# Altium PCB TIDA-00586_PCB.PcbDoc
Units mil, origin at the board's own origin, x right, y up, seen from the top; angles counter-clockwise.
Board outline 4500 x 1700 mil, 4 copper layers (Top Layer, MidLayer1, MidLayer2, Bottom Layer), stack 61.2 mil thick; 69 components, 46 nets, 255 pads, 91 vias.
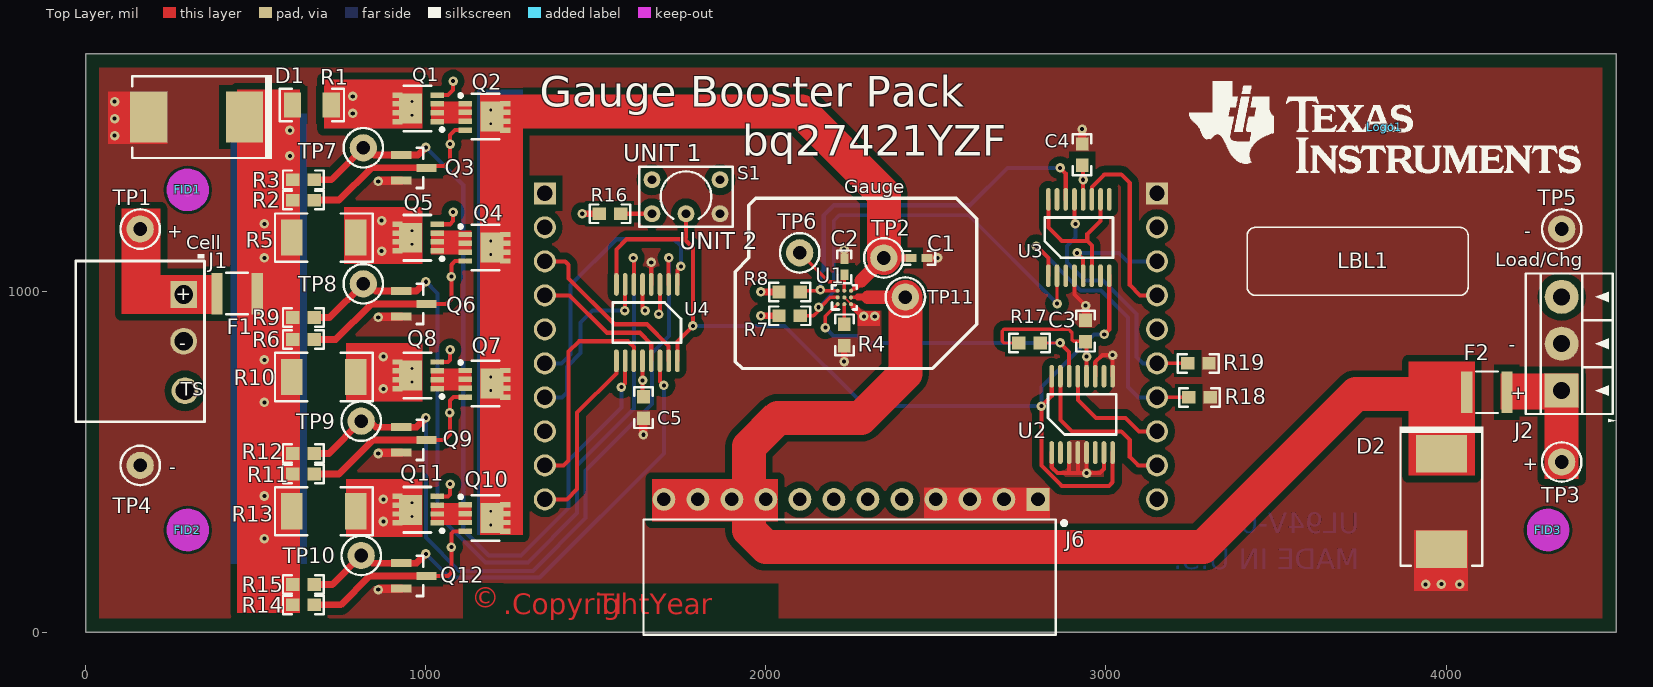
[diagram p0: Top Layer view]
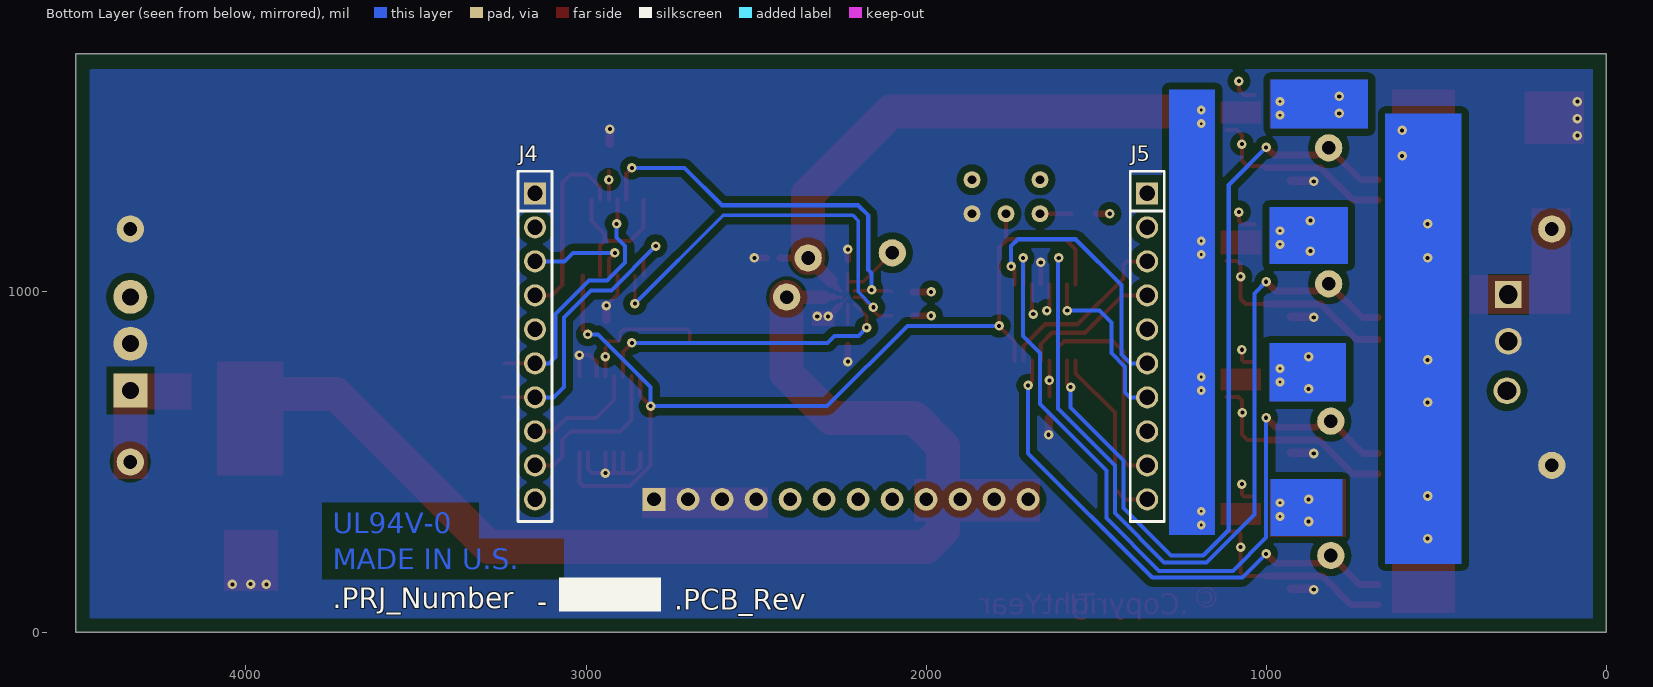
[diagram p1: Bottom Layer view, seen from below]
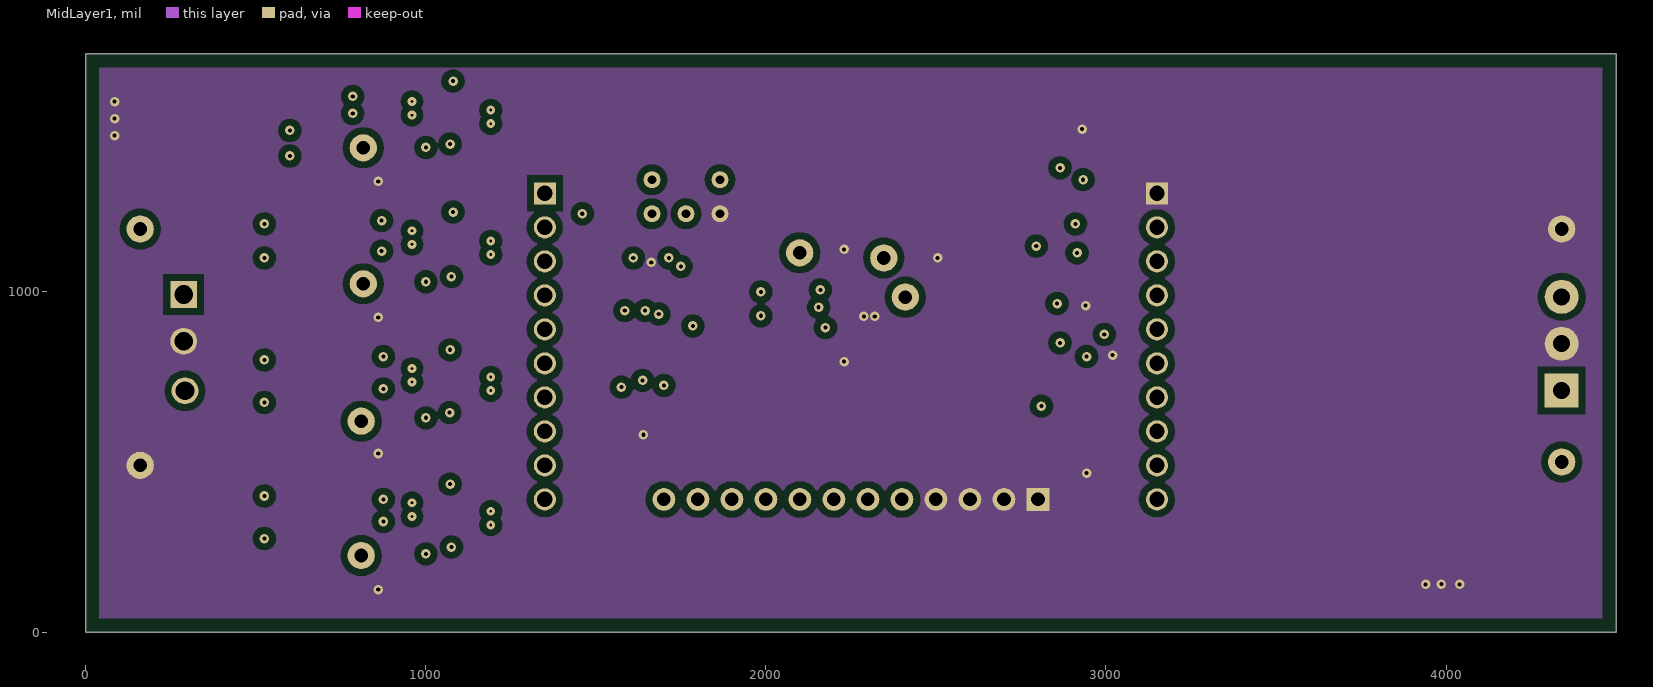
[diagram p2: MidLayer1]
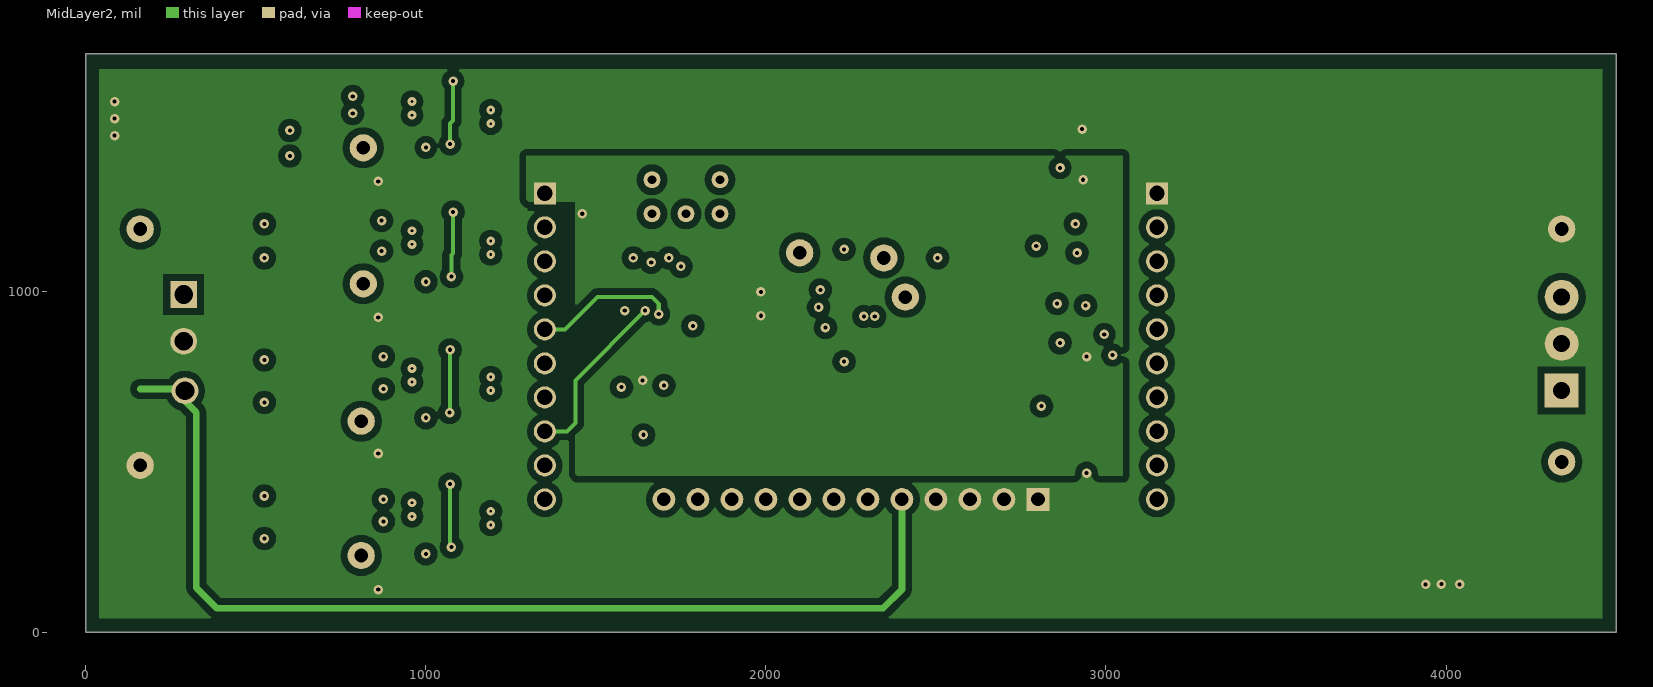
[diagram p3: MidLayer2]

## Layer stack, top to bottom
Top Solder: solder mask 0.4, Solder Resist, Dk 3.5
Top Layer: signal copper 2.8
Dielectric1: core 8, FR-4, Dk 4.8
MidLayer1: signal copper 2.8
Dielectric2: prepreg 34, FR-4, Dk 4.8
MidLayer2: signal copper 2.8
Dielectric3: core 8, FR-4, Dk 4.8
Bottom Layer: signal copper 2.8
Bottom Solder: solder mask 0.4, Solder Resist, Dk 3.5

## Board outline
0,0 0,1700 4500,1700 4500,0 0,0

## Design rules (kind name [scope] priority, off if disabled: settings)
AcuteAngle [All] p1: minimum=4.50000000000000E+0001 checktracksonly=FALSE
AssemblyTestPointUsage [All] p1: valid=2
Clearance Clearance_BoardEdge_MountingHoles [OnCopper and InComponentClass('Mounting Holes') vs IsKeepOut] p1: gap=8
Clearance Clearance_BoardEdge_Poly [OnCopper and InPoly vs IsKeepOut] p2: gap=8
Clearance Clearance_BoardEdge [OnCopper and Not InComponentClass('Logo') and not InComponentClass('FiducialMark') and not InRegion(1000,500,4000,800) and Not IsKeepout vs IsKeepOut] p3: gap=20
Clearance Clearance_Poly [InPolygon] p4: gap=20
Clearance [All] p5: gap=5
ComponentClearance ComponentClearance_Shunt [InComponentClass('Header') vs InComponentClass('Shunt')] p1: gap=0 collisioncheckmode=3 verticalgap=0 showdistances=FALSE
ComponentClearance ComponentClearance_Logo [InComponentClass('Logo')] p2: gap=5 collisioncheckmode=3 verticalgap=5 showdistances=FALSE
ComponentClearance ComponentClearance_ScrewToNut [(HasFootprint('NY PMS 440 0025 PH')) vs (HasFootprint('Keystone_1902C'))] p3: gap=5 collisioncheckmode=3 verticalgap=10 showdistances=FALSE
ComponentClearance ComponentClearance_MountingHoles [InComponentClass('Mounting Holes')] p4: gap=250 collisioncheckmode=3 verticalgap=100000 showdistances=FALSE
ComponentClearance ComponentClearance_SmallPassives [HasFootprint('0201*') or HasFootprint('0402*') or HasFootprint('0508') or HasFootprint('0603*') or HasFootprint('0612') or HasFootprint('0805*') or HasFootprint('0815*') or HasFootprint('0830*') or HasFootprint('1206*') or HasFootprint('1210*') or HasFootprint('1808*') or HasFootprint('1812*') or HasFootprint('1825*') or HasFootprint('2010*') or HasFootprint('2220*') or HasFootprint('2225*') or HasFootprint('2512*') or HasFootprint('2728*') or HasFootprint('3518*') vs HasFootprint('0201*') or HasFootprint('0402*') or HasFootprint('0508') or HasFootprint('0603*') or HasFootprint('0612') or HasFootprint('0805*') or HasFootprint('0815*') or HasFootprint('0830*') or HasFootprint('1206*') or HasFootprint('1210*') or HasFootprint('1808*') or HasFootprint('1812*') or HasFootprint('1825*') or HasFootprint('2010*') or HasFootprint('2220*') or HasFootprint('2225*') or HasFootprint('2512*') or HasFootprint('2728*') or HasFootprint('3518*')] p5: gap=8 collisioncheckmode=3 verticalgap=8 showdistances=FALSE
ComponentClearance ComponentClearance_THtoSMT [IsThruComponent vs IsSMTComponent] p6: gap=8 collisioncheckmode=3 verticalgap=8 showdistances=FALSE
ComponentClearance ComponentClearance_THtoTH [IsThruComponent vs IsThruComponent] p7: gap=8 collisioncheckmode=3 verticalgap=8 showdistances=FALSE
ComponentClearance [All] p8: gap=8 collisioncheckmode=3 verticalgap=8 showdistances=FALSE
DiffPairsRouting [All] p1: maxlimit=100 minlimit=10 mostfreqgap=10 toplayer_minwidth=15 toplayer_maxwidth=15 toplayer_prefwidth=15 midlayer1_minwidth=15 midlayer1_maxwidth=15 midlayer1_prefwidth=15 midlayer2_minwidth=15 midlayer2_maxwidth=15 midlayer2_prefwidth=15 bottomlayer_minwidth=15 bottomlayer_maxwidth=15 bottomlayer_prefwidth=15 maxuncoupledlength=1000
FabricationTestPointUsage TestPointUsage [All] p1: valid=2 allowmultiple=FALSE
FabricationTestpoint Testpoint [All] p1: side=3 testpointundercomponent=TRUE minsize=40 maxsize=100 preferedsize=60 minholesize=0 maxholesize=40 preferedholesize=32 testpointgrid=1 allowsidetop=TRUE allowsidebottom=TRUE usegrid=TRUE gridtolerance=0.01
FanoutControl Fanout_LCC [IsLCC] p1: bgadir=Out bgaviamode=Centered fanoutstyle=Auto fanoutdirection=Alternating viagrid=1 // Fanout_LCC (Default Rule)
FanoutControl Fanout_BGA [IsBGA] p2: bgadir=Out bgaviamode=Centered fanoutstyle=Auto fanoutdirection=Alternating viagrid=1 // Fanout_BGA (Default Rule)
FanoutControl Fanout_Default [All] p4: bgadir=Out bgaviamode=Centered fanoutstyle=Auto fanoutdirection=Alternating viagrid=1 // Fanout_Default (Default Rule)
FanoutControl Fanout_Small [(CompPinCount < 5)] p5: bgadir=Out bgaviamode=Centered fanoutstyle=Auto fanoutdirection=OutThenIn viagrid=1 // Fanout_Small (Default Rule)
HoleSize [All] p1: absolutevalues=TRUE maxlimit=251 minlimit=5 maxpercent=80.000 minpercent=20.000
MinimumAnnularRing MinimumAnnularRing_ThermalPadVias [IsVia and InAnyComponent] p1: minimumring=5
MinimumAnnularRing [All] p2: minimumring=5
MinimumSolderMaskSliver MinimumSolderMaskSliver_Logo [InComponentClass('Logo') vs InComponentClass('Logo')] p1: minsoldermaskwidth=0.7
MinimumSolderMaskSliver [All] p2: minsoldermaskwidth=3.94
PlaneClearance [All] p1: clearance=10
PlaneConnect [All] p1: planeconnectstyle=Direct reliefexpansion=10 reliefentries=4 reliefconductorwidth=10 reliefairgap=10
PolygonConnect [All] p1: connectstyle=Direct reliefconductorwidth=10 reliefentries=4 polygonreliefangle="90 Angle" airgapwidth=10
RoutingVias ThermalPadVias [IsVia and InAnyComponent] p1: holewidth=7.87 width=19.68 viastyle="Through Hole" minholewidth=7.87 minwidth=19.68 maxholewidth=12.99 maxwidth=23.62
RoutingVias [All] p2: holewidth=12 width=24 viastyle="Through Hole" minholewidth=5 minwidth=10 maxholewidth=40 maxwidth=65
SMDToCorner [All] p1: distance=30000
SilkToSilkClearance [All] p1: silktosilkclearance=5
SilkToSolderMaskClearance SilkscreenOverComponentPads [IsPad] p1: minsilkscreentomaskgap=5 clearancetoexposedcopper=TRUE
SolderMaskExpansion [All] p1: expansion=1.97
UnpouredPolygon [All] p1: allowunpoured=FALSE
Width [All] p1: maxlimit=100 minlimit=6 preferedwidth=10 checkconnectedcopper=TRUE
14 further rules are at their usual default settings.

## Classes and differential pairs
component class Logo: Logo1
component class PR2183E3_Hdwr: FID1 FID2 FID3 LBL1 Logo1 ZZ1 ZZ2 ZZ3
component class FiducialMark: FID1 FID2 FID3
component class AssemblyNote: ZZ1 ZZ2 ZZ3
component class Label: LBL1
component class PR2183E3_Gauge: C1 C2 C3 C4 C5 D1 D2 F1 F2 J1 J2 J4 J5 J6 Q1 Q2 Q3 Q4 Q5 Q6 Q7 Q8 Q9 Q10 Q11 Q12 R1 R2 R3 R4 R5 R6 R7 R8 R9 R10 R11 R12 R13 R14 R15 R16 R17 R18 R19 S1 TP1 TP2 TP3 TP4 TP5 TP6 TP7 TP8 TP9 TP10 TP11 U1 U2 U3 U4

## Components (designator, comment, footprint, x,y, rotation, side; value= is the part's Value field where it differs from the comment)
C1 "GRM155R61A105KE15D" 0402 2450,1100 r0 top
C2 "GRM155R60J474KE19D" 0402 2230.63,1073.88 r90 top
C3 "C0603C104K3RACTU" 0603 2940,885 r90 top
C4 "C0603C104K3RACTU" 0603 2930,1403.7 r90 top
C5 "C0603C104K3RACTU" 0603 1640,660 r270 top
D1 "1.5SMC6.8A" SMC 326.16,1514 r180 top
D2 "1.5SMC6.8A" SMC 3986.16,384 r270 top
F1 "RF1824-000" FUSE_LR2 445,995 r0 top
F2 "RF1824-000" FUSE_LR2 4120,705 r0 top
FID1 "Fiducial" Fiducial10-30 300,1300 r0 top
FID2 "Fiducial" Fiducial10-30 300,300 r0 top
FID3 "Fiducial" Fiducial10-30 4300,300 r0 top
J1 "OSTOQ031251" On-Shore_OSTOQ031251 160,855 r270 top
J2 "ED555/3DS" TERM_BLK_ED555-3DS 4340,710 r90 top
J4 "SSW-110-24-F-S" CONN_SSW-110-23-F-S 3150,1290 r90 bottom locked
J5 "SSW-110-24-F-S" CONN_SSW-110-23-F-S 1350,1290 r90 bottom locked
J6 "PPPC121LGBN-RC" SULLINS_PPPC121LGBN-RC 2250,390 r0 top locked
LBL1 "Size: 0.65\" x 0.20 \"" Label_650x200 3740,1090 r0 top
Logo1 "Texas Instruments" TI_Stacked_Overlay_Medium 3820,1485 r0 top
Q1 "SI7615ADN-T1-GE3" PowerPAK_1212-8 975,1540 r180 top
Q2 "SI7615ADN-T1-GE3" PowerPAK_1212-8 1175,1515 r0 top
Q3 "2N7002-7-F" SOT-23 965,1365 r0 top
Q4 "SI7615ADN-T1-GE3" PowerPAK_1212-8 975,1160 r180 top
Q5 "SI7615ADN-T1-GE3" PowerPAK_1212-8 1175,1130 r0 top
Q6 "2N7002-7-F" SOT-23 965,965 r0 top
Q7 "SI7615ADN-T1-GE3" PowerPAK_1212-8 975,755 r180 top
Q8 "SI7615ADN-T1-GE3" PowerPAK_1212-8 1175,730 r0 top
Q9 "2N7002-7-F" SOT-23 965,565 r0 top
Q10 "SI7615ADN-T1-GE3" PowerPAK_1212-8 975,360 r180 top
Q11 "SI7615ADN-T1-GE3" PowerPAK_1212-8 1175,335 r0 top
Q12 "2N7002-7-F" SOT-23 965,165 r0 top
R1 "CRCW12060000Z0EA" 1206 665,1550 r0 top
R2 "CRCW06032M00FKEA" 0603 640,1270 r180 top
R3 "CRCW06032M00FKEA" 0603 640,1330 r180 top
R4 "CRCW0603100KFKEA" 0603 2230.63,873.88 r90 top
R5 "CSRN2010FKR100" 2010M 700,1160 r0 top
R6 "CRCW06032M00FKEA" 0603 640,860 r180 top
R7 "CRCW06031K00FKEA" 0603 2070,930 r180 top
R8 "CRCW06031K00FKEA" 0603 2070,1000 r180 top
R9 "CRCW06032M00FKEA" 0603 640,925 r180 top
R10 "CSRN2010FKR200" 2010M 700,750 r0 top
R11 "CRCW06032M00FKEA" 0603 640,465 r180 top
R12 "CRCW06032M00FKEA" 0603 640,525 r180 top
R13 "CSRN2010FKR400" 2010M 700,355 r0 top
R14 "CRCW06032M00FKEA" 0603 640,80 r180 top
R15 "CRCW06032M00FKEA" 0603 640,140 r180 top
R16 "CRCW060310K0FKEA" 0603 1541.65,1230 r180 top
R17 "CRCW06031M00FKEA" 0603 2775,850 r180 top
R18 "CRCW06032M00FKEA" 0603 3275,690 r180 top
R19 "CRCW06032M00FKEA" 0603 3271.5,790 r180 top
S1 "G12AP" SW_G1xAP 1765,1280 r0 top
TP1 "5000" Keystone5000 160,1185 r0 top
TP2 "5000" Keystone5000 2346.75,1100 r0 top
TP3 "5000" Keystone5000 4340,500 r0 top
TP4 "5001" Keystone5001 160,490 r0 top
TP5 "5001" Keystone5001 4340,1185 r0 top
TP6 "5000" Keystone5000 2099.35,1115 r0 top
TP7 "5002" Keystone5002 816.16,1424 r0 top
TP8 "5002" Keystone5002 816.16,1024 r0 top
TP9 "5002" Keystone5002 810,620 r0 top
TP10 "5002" Keystone5002 810,225 r90 top
TP11 "5000" Keystone5000 2410,985 r0 top
U1 "BQ27421YZFR-G1A" YZF0009AKAL 2230.66,983.85 r90 top
U2 "TS3A44159PWR" PW0016A_N 2930,640 r90 top
U3 "TS3A44159PWR" PW0016A_N 2920,1160 r90 top
U4 "TS3A44159PWR" PW0016A_N 1650,910 r270 top
ZZ1 "This Assembly Note is for PCB labels only" AssemblyNoteLabel 205,7588 r0 top
ZZ2 "Mating Plug" AssemblyNote 205,7479.11 r0 top
ZZ3 "J4, J5 Must be inserted from the bottom with the pins facing up." AssemblyNote 205,7365 r0 top

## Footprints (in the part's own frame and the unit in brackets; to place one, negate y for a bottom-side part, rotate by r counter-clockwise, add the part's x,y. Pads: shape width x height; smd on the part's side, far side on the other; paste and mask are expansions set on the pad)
0402 [mm] "0402 from SM-752 data"
  rect 0.8x0.6 smd: 1(-0.6,0) 2(0.6,0)
  silkscreen extent -1.22,-0.52 1.22,0.52, body extent -0.55,-0.3 0.55,0.3, height 0.6
0603 [mm] "0603 from SM-752 data"
  rect 1x0.95 smd: 1(-0.8,0) 2(0.8,0)
  silkscreen extent -1.52,-0.69 1.52,0.69, body extent -0.87,-0.47 0.87,0.47, height 0.85
1206 [mm] "1206 from SM-752 data"
  rect 1.3x1.85 smd: 1(-1.45,0) 2(1.45,0)
  silkscreen extent -2.4,-1.21 2.4,1.21, body extent -1.7,-0.9 1.7,0.9, height 1.35
2010M [mm]
  rect 1.6x2.7 smd: 1(-2.4,0) 2(2.4,0)
  silkscreen extent -3.65,-1.8 3.65,1.8, body extent -2.73,-1.45 2.73,1.45, height 1.66
AssemblyNote [mil] "Assembly Note"
AssemblyNoteLabel [mil] "Assembly Note for PCB Labels"
CONN_SSW-110-23-F-S [mm] "SAMTEC"
  rect 1.65x1.65 hole 1.15: 1(0,0)
  round 1.65 hole 1.15: 2(-2.54,0) 3(-5.08,0) 4(-7.62,0) 5(-10.16,0) 6(-12.7,0) 7(-15.24,0) 8(-17.78,0) 9(-20.32,0) 10(-22.86,0)
  silkscreen extent -24.51,-1.27 1.65,1.27, body extent -24.43,-1.27 1.57,1.27, height 8.59
Fiducial10-30 [mm]
  round 1 smd paste-0.5 mask+1: 1(0,0)
  Top Layer keep-out circle w1.678: c0,0 r0.75
FUSE_LR2 [mm] "TE Connectivity"
  rect 0.85x3.1 smd: 1(-1.5,0) 2(1.5,0)
  silkscreen extent -0.8,-1.55 0.8,1.55, body extent -1.71,-1.4 1.71,1.4, height 1
Keystone5000 [mil] "For Keystone 500x miniature loop terminals"
  round 80 hole 40: 1(0,0)
  silkscreen extent -58,-58 58,58, body extent -49,-49 49,49, height 182
Keystone5001 [mil] "For Keystone 500x miniature loop terminals"
  round 80 hole 40: 1(0,0)
  silkscreen extent -58,-58 58,58, body extent -49,-49 49,49, height 182
Keystone5002 [mil] "For Keystone 500x miniature loop terminals"
  round 80 hole 40: 1(0,0)
  silkscreen extent -58,-58 58,58, body extent -49,-49 49,49, height 182
Label_650x200 [mil] "Thermal Transfer Label"
  round 1 on Mech13: 0(0,0)
  silkscreen extent -325,-100 325,100, body extent -326,-101 326,101, height 1
On-Shore_OSTOQ031251 [mm] "TERM BLOCK 3x1, 3.5mm, TH"
  rect 2x2 hole 1.4: 1(-3.5,3.25)
  round 2 hole 1.4: 2(0,3.25) 3(3.7,3.35)
  silkscreen extent -6.5,-4.8 6,4.8, body extent -5.95,-4.75 5.95,4.75, height 7
PowerPAK_1212-8 [mil] "Vishay PowerPAK 1212-8, Body 3.4x3.2mm (max), Pitch 0.65mm, IPC Medium Density"
  rect 39x16 smd mask+2.01: 1(-58.75,39) 2(-58.75,13) 3(-58.75,-13) 4(-58.75,-39)
  rect 30x16 smd mask+2.01: 5(58.75,-39) 6(58.75,-13) 7(58.75,13) 8(58.75,39)
  rect 68x88 smd mask+2.01: 9(19.75,0.61)
  silkscreen extent -78,-66 40,68, body extent -65,-65 65,65, height 43
PW0016A_N [mm] "TSOP, 16-Leads, Body 5x4.4mm, Pitch 0.65mm, IPC Medium Density"
  oval 1.7x0.35 smd: 1(-2.85,2.275) 2(-2.85,1.625) 3(-2.85,0.975) 4(-2.85,0.325) 5(-2.85,-0.325) 6(-2.85,-0.975) 7(-2.85,-1.625) 8(-2.85,-2.275) 9(2.85,-2.275) 10(2.85,-1.625) 11(2.85,-0.975) 12(2.85,-0.325) 13(2.85,0.325) 14(2.85,0.975) 15(2.85,1.625) 16(2.85,2.275)
  silkscreen extent -1.5,-2.55 1.5,2.55, body extent -3.21,-2.5 3.21,2.5, height 0.98
SMC [mil] "Molded Diode, 2-Leads, Body 6.9x5.8mm, IPC Medium Density, based on OnSemi component dimensions and land patterns"
  rect 110x150 smd: 1(-140.49,0) 2(140.49,0)
  silkscreen extent -221,-124 189,123, body extent -156,-116 156,116, height 91
SOT-23 [mm] "SOT23, 3-Leads, Body 2.9x1.3mm, Pitch 0.95mm, Lead Span 2.5mm, IPC Medium Density"
  rect 1.5x0.6 smd: 1(-0.95,0.95) 2(-0.95,-0.95) 3(0.95,0)
  silkscreen extent 0.2,-1.5 0.7,1.5, body extent -1.16,-1.45 1.21,1.45, height 1
SULLINS_PPPC121LGBN-RC [mm] "SULLINS"
  rect 1.7x1.7 hole 1.016: 1(13.97,0)
  round 1.7 hole 1.016: 2(11.43,0) 3(8.89,0) 4(6.35,0) 5(3.81,0) 6(1.27,0) 7(-1.27,0) 8(-3.81,0) 9(-6.35,0) 10(-8.89,0) 11(-11.43,0) 12(-13.97,0)
  silkscreen extent -15.49,-10.1 16.07,-1.5, body extent -15.49,-10.08 15.24,0.23, height 2.52
SW_G1xAP [mil] "Switch, NKK G Series"
  round 50 hole 26: 1(-100,50) 3(100,50) 4(-100,-50) 5(0,-50) 6(100,-50)
  silkscreen extent -138,-88 138,89, body extent -138,-88 138,89, height 424
TERM_BLK_ED555-3DS [mm]
  rect 2.54x2.54 hole 1.27: 1(0,0)
  round 2.54 hole 1.27: 2(3.5,0) 3(7,0)
  silkscreen extent -2.36,-4.09 8.75,2.67, body extent -1.75,-3.83 8.75,2.67, height 8.2
TI_Stacked_Overlay_Medium [mil]
  silkscreen extent -576,-136 576,134
YZF0009AKAL [mm] "BGA, 9-Leads, Body 1.6205x1.58mm, Pitch 0.5mm"
  round 0.3 smd paste-0.15 mask+0.05: A1(-0.5,0.5) A2(0,0.5) A3(0.5,0.5) B1(-0.5,0) B2(0,0) B3(0.5,0) C1(-0.5,-0.5) C2(0,-0.5) C3(0.5,-0.5)
  silkscreen extent -0.9,-0.93 0.9,0.93, body extent -0.8,-0.83 0.8,0.83, height 0.63

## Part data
C1: "CAP, CERM, 1uF, 10V, +/-10%, X5R, 0402"
C2: "CAP, CERM, 0.47uF, 6.3V, +/-10%, X5R, 0402"
C3 C4 C5: "CAP, CERM, 0.1uF, 25V, +/-10%, X7R, 0603"
D1 D2: "Diode, TVS, Uni, 6.8V, 1500W, SMC"
F1 F2: "Fuse, Resettable, 1.9A, 6V, SMD"
FID1 FID2 FID3: "Fiducial mark.  There is nothing to buy or mount."
J1: "Header, 3x1 3.5mm, TH"
J2: "Terminal Block, 6A, 3.5mm Pitch, 3-Pos, TH"
J4 J5: library part SSW-110-23-F-S, "Connector, Receptacle, 100mil, 10x1, Gold plated, TH"
J6: "Header, 12x1, 100mil, R/A, TH"
LBL1: library part THT-14-423-10, "Thermal Transfer Printable Labels, 0.650\" W x 0.200\" H - 10,000 per roll"
Logo1: library part TI_Logo, "Texas Instrument Corporate Signature"
Q1 Q2 Q4 Q5 Q7 Q8 Q10 Q11: "MOSFET, P-CH, -20V, -22.1A, PowerPAK 1212"
Q3 Q6 Q9 Q12: "MOSFET, N-CH, 60V, 0.17A, SOT-23"
R1: "RES, 0 ohm, 5%, 0.25W, 1206"
R2 R3 R6 R9 R11 R12 R14 R15 R18 R19: "RES, 2.00Meg ohm, 1%, 0.1W, 0603"
R4: "RES, 100k ohm, 1%, 0.1W, 0603"
R5: "RES, 0.1 ohm, 1%, 1W, 2010"
R7 R8: "RES, 1.00k ohm, 1%, 0.1W, 0603"
R10: "RES, 0.2 ohm, 1%, 1W, 2010"
R13: "RES, 0.4 ohm, 1%, 1W, 2010"
R16: "RES, 10.0k ohm, 1%, 0.1W, 0603"
R17: "RES, 1.00Meg ohm, 1%, 0.1W, 0603"
S1: "Switch, Toggle, SPDT 1Pos, TH"
TP1 TP2 TP3 TP6 TP11: "Test Point, Miniature, Red, TH"
TP4 TP5: "Test Point, Miniature, Black, TH"
TP7 TP8 TP9 TP10: "Test Point, Miniature, White, TH"
U1: "System-Side Impedance Track Fuel Gauge With Integrated Sense Resistor, YZF0009AKAL"
U2 U3 U4: "0.45 ohm QUAD SPDT ANALOG SWITCH QUAD-CHANNEL 2:1 MULTIPLEXER/DEMULTIPLEXER WITH TWO CONTROLS, PW0016A"
ZZ1: library part AssemblyNoteLabel
ZZ2: library part AssemblyNote, "This is the mating Plug for Connector J1"
ZZ3: library part AssemblyNote

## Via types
v1: diameter 28, hole 12, Top Layer to Bottom Layer, 75 vias
v2: diameter 26, hole 8, Top Layer to Bottom Layer, tented top, 16 vias

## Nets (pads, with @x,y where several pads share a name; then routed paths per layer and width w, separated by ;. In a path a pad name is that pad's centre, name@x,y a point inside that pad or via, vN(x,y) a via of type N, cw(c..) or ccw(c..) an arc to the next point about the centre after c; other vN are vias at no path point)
3.3VDC: C3.1 C4.1 C5.1 J5.1 R7.2 R8.2 R16.2 R17.2 U2.12 U3.12 U4.12 | length 762.2
  Top Layer w10: R17.2 2700,850 2695,855 2695,885 2700,890 2890,890 2900,880 2900,860 2905,855 2938.5,855 C3.1
  Top Layer w12: C5.1@1637.2,694.29 v1(1637.2,740) U4.12 ; U3.12 v1(2932.8,1330) C4.1@2932.8,1355.71 ; U2.12 v1(2942.8,810) C3.1@2942.8,835.71
  Top Layer w20: v1(1460,1230) R16.2@1500.18,1230 ; v1@1990,930 R7.2 ; v1@1990,1000 R8.2
  other v1: 1985,930 1985,1000
B1_1: J5.3 U4.15 | length 517.9
  Top Layer w12: J5.3@1370,1100 1380,1090 1410,1090 1420,1080 1420,1040 1555,905 1650,905 1713.98,841.02 U4.15
B1_2: J5.4 U4.13 | length 405.5
  Top Layer w12: J5.4@1370,1000 1380,990 1422.15,990 1532.15,880 1630,880 1662.8,847.2 U4.13
B2_1: J5.5 U4.3 | length 480.6
  Top Layer w12: v1@1688.39,938.39 U4.3
  MidLayer2 w12: J5.5@1370,900 1380,890 1409.25,890 1504.25,985 1665,985 1685,965 v1(1685,935)
B2_2: J5.6 U4.1 | length 780.3
  Top Layer w12: U4.1 1739.57,1064.57 v1(1750,1075)
  Bottom Layer w12: J5.6@1370,800 1380,790 1399.14,790 1425,815.86 1425,1020 1560,1155 1730,1155 1750,1135 v1(1750,1075)
B3_1: J5.7 U4.7 | length 491.6
  Top Layer w12: v1@1586.02,946.02 U4.7
  Bottom Layer w12: J5.7@1374.25,695.75 1380,690 1400,690 1415,705 1415,780 1455,820 1455,910 1490,945 v1(1585,945)
B3_2: J5.8 U4.5 | length 569.4
  Top Layer w12: v1@1637.2,952.2 U4.5
  MidLayer2 w12: J5.8@1370,600 1380,590 1415,590 1440,615 1440,740 v1(1645,945)
B4_1: J5.9 U4.11 | length 631.9
  Top Layer w12: J5.9@1370,500 1380,490 1405,490 1420,505 1420,825 1450,855 1595,855 1611.61,838.39 U4.11
B4_2: J5.10 U4.9 | length 517.2
  Top Layer w12: J5.10@1370,400 1380,390 1415,390 1445,420 1445,645 1560.43,760.43 U4.9
BIN: R4.2 U1.B1 | length 58.8
  Top Layer w10: R4.2@2230.66,905.41 U1.B1
BINARY_1: Q12.1 R15.1 TP10.1 U4.14 | length 1542.3
  Top Layer w12: U4.14 1688.39,736.61 v1(1700,725)
  Top Layer w20: R15.1 725,140 TP10.1 820,225 842.6,202.4 Q12.1 972.4,202.4 v1(1000,230)
  Bottom Layer w12: v1(1000,230) 1070,160 1335,160 1700,525 v1(1700,725)
BINARY_2: Q9.1 R12.1 TP9.1 U4.2 | length 2256.5
  Top Layer w12: U4.2 v1@1713.98,1098.98
  Top Layer w20: R12.1 715,525 TP9.1 834.97,620 852.57,602.4 Q9.1 972.4,602.4 v1(1000,630)
  Bottom Layer w12: v1(1000,630) 1000,278.15 1098.15,180 1315,180 1470,335 1470,475 1665,670 1665,820.77 1715,870.77 v1(1715,1100)
BINARY_3: Q6.1 R9.1 TP8.1 U4.6 | length 2513.3
  Top Layer w12: U4.6 v1@1611.61,1098.39
  Top Layer w20: R9.1 717.16,925 TP8.1 831,1024 852.6,1002.4 Q6.1 972.4,1002.4 v1(1000,1030)
  Bottom Layer w12: v1(1000,1030) 1034.23,995.77 1034.23,345.77 1175,205 1300,205 1445,350 1445,490 1611.61,656.61 1611.61,1098.39 v1(1610,1100)
BINARY_4: Q3.1 R3.1 TP7.1 U4.10 | length 2456.9
  Top Layer w12: v1(1575,720) 1586.02,731.02 U4.10
  Top Layer w20: R3.1 722.16,1330 TP7.1 826,1424 847.6,1402.4 Q3.1 977.4,1402.4 v1(1000,1425)
  Bottom Layer w12: v1(1000,1425) 1110,1315 1110,300 1185,225 1280,225 1420,365 1420,505 1575,660 v1(1575,720)
CHG/LOAD: D2.1 F2.1 J6.9 J6.10 J6.11 J6.12 TP11.1 U1.C2 | length 3355.8
  Top Layer w11: U1.C2@2250.36,983.85 2270,985
  Top Layer w20: 2270,985 2300,985
  Top Layer w40: 2300,985 TP11.1@2400,985
  Top Layer w100: 1950,390 1950,300 2000,250 3285,250 3735,700 3950,700 ; 1950,410 1950,545 2035,630 2280,630 2410,760 TP11.1
CS_1: J4.4 U3.11 | length 549.9
  Top Layer w12: U3.11 2958.39,1308.39 2995,1345 3045,1345 3070,1320 3070,1020 3100,990 3120,990 J4.4@3130,1000
CS_2: J4.3 U3.5 | length 304.1
  Top Layer w12: v1(2915,1115) 2932.8,1097.2 U3.5
  Bottom Layer w12: v1(2915,1115) 3038.88,1115 3063.88,1090 3120,1090 J4.3@3130,1100
GND: C1.2 C2.2 C3.2 C4.2 C5.2 D1.2 D2.2 J1.2 J2.2 J4.1 J6.1 J6.2 J6.3 J6.4 Q3.2 Q6.2 Q9.2 Q12.2 R4.1 R18.1 R19.1 S1.6 TP4.1 TP5.1 U1.B2 U1.C1 U2.1 U2.3 U2.4 U2.5 U2.7 U2.9 U2.11 U3.4 U4.4 | length 2169.5
  Top Layer w6: U1.B2 U1.C1@2250.36,964.15
  Top Layer w12: U4.4 v1(1662.8,1087.2) ; U1.C1@2250.36,964.15 2258.74,955.77 ; U2.1 2840.43,484.57 2857.2,467.8 2890,467.8 2891.61,469.41 U2.3 ; 2891.61,467.8 2917.2,467.8 ; U3.4 2907.2,992.8 v1(2940,960) ; U2.4 2917.2,467.8 ; U2.5 v1(2942.8,467.2) ; U2.11 2968.39,793.39 2989.57,814.57 v1(3019.57,814.57) U2.9 ; U2.7 2993.98,478.98 2982.2,467.2 v1(2942.8,467.2) ; 2917.2,467.8 2917.8,467.2 v1(2942.8,467.2)
  Top Layer w20: v1@2230.63,800.63 R4.1 ; C2.2@2230.63,1093.57 C2.2 v1@2230.63,1124.37 ; 2258.74,955.77 2280,934.51 2280,920 v1(2288,928) v1@2290,930 ; C1.2@2469.69,1100 C1.2 v1(2505,1100)
  Top Layer w25: v1(85,1460) 185,1460 185.67,1460.67 D1.2 ; v1@86,1514 D1.2 ; v1@90,1560 185,1560 185.67,1559.33 D1.2 ; v1@862.6,127.6 Q12.2 ; v1@862.6,527.6 Q9.2 ; v1@862.6,927.6 Q6.2 ; v1@862.6,1327.6 Q3.2 ; v1(1640,580) C5.2 ; C4.2 v1(2930,1478.7) ; C3.2 v1(2940,960) ; v1(3940,140) 3940,240 3943.51,243.51 D2.2 ; v1(3986.16,141.16) D2.2 ; v1(4040,140) 4040,240 4036.49,243.51 D2.2
  other v1: 860,125 860,525 2230,795 860,925 2320,928 2230,1125 860,1325 85,1510 85,1560
GPOUT: R17.1 U1.A1 U2.14 | length 960
  Top Layer w10: v1(2175,895) 2175,928.19 U1.A1 ; R17.1 v1(2865,850)
  Top Layer w12: v1(2865,850) 2891.61,823.39 U2.14
  Bottom Layer w12: v1(2175,895) 2199.25,870.75 2268.74,870.75 2289.5,850 v1(2865,850)
GPOUT_1: J4.9 U2.15 | length 478.3
  Top Layer w12: U2.15 2866.02,623.98 2900,590 3045,590 3070,565 3070,515 3095,490 3120,490 J4.9@3128,498
GPOUT_2: J4.8 U2.13 | length 310.6
  Top Layer w12: U2.13 2917.2,682.8 2970.24,629.76 3057.31,629.76 3097.07,590 J4.8@3120,590
I2C_SCL_B: J4.6 R19.2 U3.13 | length 729.6
  Top Layer w10: J4.6 R19.2
  Top Layer w12: v1@2907.2,1202.8 U3.13
  Bottom Layer w12: v1(2910,1200) 2910,1160 2885,1135 2885,1086.23 2937.62,1033.62 2991.38,1033.62 3090,935 3090,808.34 3108.34,790 3120,790 J4.6@3130,800
I2C_SDA_B: J4.7 R18.2 U3.1 | length 857.9
  Top Layer w10: J4.7 R18.2@3246.95,690
  Top Layer w12: v1(2795,1135) 2830.43,1099.57 U3.1
  Bottom Layer w12: v1(2795,1135) 2925.51,1004.49 2985,1004.49 3065,924.49 3065,720 3095,690 J4.7
NetC1_1: C1.1 Q2.5 Q2.6 Q2.7 Q2.8 Q2.9 Q5.5 Q5.6 Q5.7 Q5.8 Q5.9 Q8.5 Q8.6 Q8.7 Q8.8 Q8.9 Q11.5 Q11.6 Q11.7 Q11.8 Q11.9 TP2.1 U1.C3 | length 1580.3
  Top Layer w10: U1.C3@2250.36,1003.55 U1.C3@2250.36,1003.61
  Top Layer w11: U1.C3@2250.36,1003.61 2265,1015
  Top Layer w20: 2265,1015 2280,1033.25 ; TP2.1 C1.1 C1.1@2430.32,1100
  Top Layer w40: 2280,1033.25 TP2.1
  Top Layer w100: 1275,1530 2105,1530 2346.75,1288.25 TP2.1
  other v2: 1190.75,315 1190.75,355 1190.75,710 1190.75,750 1190.75,1110 1190.75,1150 1190.75,1495 1190.75,1535
NetC2_1: C2.1 TP6.1 U1.B3 | length 217.1
  Top Layer w10: TP6.1 2184.35,1030 2230.66,1030 ; U1.B3@2230.66,1003.55 2230.66,1030 ; C2.1@2230.66,1054.16 2230.66,1030
NetD1_1: D1.1 F1.2 R1.1 R2.2 R3.2 R5.1 R6.2 R9.2 R10.1 R11.2 R12.2 R13.1 R14.2 R15.2
  other v1: 525,275 525,400 525,675 525,800 525,1100 525,1200 600,1400 600,1475
NetF1_1: F1.1 J1.1 TP1.1
NetF2_2: F2.2 J2.1 TP3.1
NetQ1_1: Q1.1 Q1.2 Q1.3 Q2.1 Q2.2 Q2.3
NetQ1_4: Q1.4 Q2.4 Q3.3 R2.1 | length 841.4
  Top Layer w12: Q3.3 1007.4,1370 1055,1370 1071.15,1386.15 v1(1071.15,1435) 1071.15,1461.15 1086,1476 Q2.4 ; Q1.4 1065.46,1579 1080,1593.54 v1(1080,1620)
  Top Layer w20: R2.1 745,1270 840,1365 Q3.3
  MidLayer2 w12: v1(1071.15,1435) 1071.15,1495 1080,1503.85 v1(1080,1620)
NetQ1_5: Q1.5 Q1.6 Q1.7 Q1.8 Q1.9 R1.2
  other v1: 785,1525 785,1575
  other v2: 959.25,1520 959.25,1560
NetQ4_1: Q4.1 Q4.2 Q4.3 Q5.1 Q5.2 Q5.3
NetQ4_4: Q4.4 Q5.4 Q6.3 R6.1 | length 867.8
  Top Layer w12: Q6.3 1060,965 1075,980 v1(1075,1045) 1075,1080 1086,1091 Q5.4 ; Q4.4 1070.46,1199 1080,1208.54 v1(1080,1235)
  Top Layer w20: R6.1 735,860 840,965 Q6.3
  MidLayer2 w12: v1(1075,1045) 1075,1108.85 1080,1113.85 v1(1080,1235)
NetQ4_5: Q4.5 Q4.6 Q4.7 Q4.8 Q4.9 R5.2
  other v1: 870,1120 870,1210
  other v2: 959.25,1140 959.25,1180
NetQ7_1: Q7.1 Q7.2 Q7.3 Q8.1 Q8.2 Q8.3
NetQ7_4: Q7.4 Q8.4 Q9.3 R11.1 | length 853.6
  Top Layer w12: Q9.3 1055,565 1071.15,581.15 1071.15,681.15 1081,691 Q8.4 ; Q7.4 1065.46,794 1071.15,799.69 v1(1071.15,830) v1@1071.15,831.16
  Top Layer w20: R11.1 745,465 845,565 Q9.3
  MidLayer2 w12: v1(1070,645) 1071.15,646.15 v1(1071.15,830)
NetQ7_5: Q7.5 Q7.6 Q7.7 Q7.8 Q7.9 R10.2
  other v1: 875,715 875,810
  other v2: 959.25,735 959.25,775
NetQ10_1: Q10.1 Q10.2 Q10.3 Q11.1 Q11.2 Q11.3
NetQ10_4: Q10.4 Q11.4 Q12.3 R14.1 | length 859.1
  Top Layer w12: Q12.3 1065,165 1075,175 v1(1075,250) 1075,290 1081,296 Q11.4 ; Q10.4 1065.46,399 1071.15,404.69 v1(1071.15,434.69) v1@1071.15,436.16
  Top Layer w20: R14.1 750,80 835,165 Q12.3
  MidLayer2 w12: v1(1071.15,434.69) 1071.15,253.85 v1(1075,250)
NetQ10_5: Q10.5 Q10.6 Q10.7 Q10.8 Q10.9 R13.2
  other v1: 875,325 875,390
  other v2: 959.25,340 959.25,380
NetR16_1: R16.1 S1.4 | length 91.9
  Top Layer w12: R16.1 S1.4
NetS1_5: S1.5 U2.8 U2.16 U3.8 U4.8 U4.16 | length 2986.1
  Top Layer w12: U4.8 1560.43,1125.43 1590,1155 1760,1155 ; U4.16 1739.57,854.57 v1(1785,900) 1785,1130 1760,1155 ; S1.5 1765,1160 1760,1155 ; U2.16 2840.43,694.49 v1(2810,664.06) 2810,490 2870,430 3009.13,430 3019.57,440.43 U2.8 ; v1(2995,875) 3009.57,889.57 U3.8
  Bottom Layer w12: v1(1785,900) 2055,900 2290.94,664.06 v1(2810,664.06) 2810,720 2965,875 v1(2995,875)
NetU3_6: U3.6 U3.10 U3.16 | length 459.7
  Top Layer w12: U3.16 2830.43,1189.57 2870,1150 2945,1150 ; U3.6 2958.39,1136.61 2945,1150 ; U3.10 2983.98,1208.98 2945,1170 2945,1150
SCL: R8.1 U1.A3 U3.14 | length 1186.4
  Top Layer w10: R8.1 2105.05,1003.55 U1.A3@2210.96,1003.55
  Top Layer w12: v1(2865,1365) 2881.61,1348.39 U3.14
  Bottom Layer w12: v1(2160,1006.3) 2160,1055 2170,1065 2170,1225 2200,1255 2600,1255 2710,1365 v1(2865,1365)
SDA: R7.1 U1.A2 U3.2 | length 1265.5
  Top Layer w10: R7.1 2140,930 2155,945 v1(2155,955) 2155,960 2165,960 2188.85,983.85 U1.A2 ; v1(2856.02,966.02) U3.2
  Bottom Layer w10: v1(2155,955) 2200,1000 2200,1210 2215,1225 2597.05,1225 v1(2856.02,966.02)
TS: J1.3 J6.5 | length 3096.4
  MidLayer2 w20: 160,714.41 255.59,714.41 325,645 325,130 385,70 2345,70 2400,125 J6.5
pads on no net: FID1.1 FID2.1 FID3.1 J2.3 J4.2 J4.5 J4.10 J5.2 J6.6 J6.7 J6.8 LBL1.0 S1.1 S1.3 U2.2 U2.6 U2.10 U3.3 U3.7 U3.9 U3.15

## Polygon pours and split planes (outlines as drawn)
GND on Top Layer "Top Layer-No Net" (solid, remove dead copper, pour order 18): 40,1660 4460,1660 4460,40 40,40
GND on Bottom Layer "Bottom Layer-No Net" (solid, remove dead copper, pour order 16): 40,1654.29 4454.29,1654.29 4460,1660 4460,40 40,40 40,1660
3.3VDC on MidLayer2 "MidLayer2-No Net" (solid, remove dead copper, pour order 8): 1305,1400 3050,1400 3050,460 1445,460 1440,465 1440,1265 1303,1265 1300,1268 1295,1273 1295,1400 1305,1400
GND on MidLayer2 "MidLayer2-No Net 1" (solid, remove dead copper, pour order 14): 40,1654.29 4460,1654.29 4460,40 40,40 40,1660
GND on MidLayer1 "MidLayer1-No Net" (solid, remove dead copper, pour order 6): 40,1660 4460,1660 4460,40 40,40 40,1660

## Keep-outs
Keep-Out Layer:
  lines w10: -5,3450 cw(c0,3450) 0,3455 ; -5,3450 cw(c0,3450) 0,3455 ; -5,3450 cw(c0,3450) 0,3455 ; -5,3450 cw(c0,3450) 0,3455 ; -5,3450 cw(c0,3450) 0,3455 ; -5,3450 cw(c0,3450) 0,3455
  text ".Layer_Name" at 577,-858.49 h60

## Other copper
Top Layer:
  rectangle net GND: 2269,900 2335,944.65
  rectangle net CHG/LOAD: 1665,325 2035,450
  rectangle net NetQ1_1: 1015,1495 1135,1560
  rectangle net NetQ4_1: 1015,1110 1135,1180
  rectangle net NetQ7_1: 1015,710 1135,775
  rectangle net NetQ10_1: 1015,315 1135,380
  rectangle net NetC1_1: 1160,285 1285,1580
  rectangle net NetQ4_5: 760,1082.61 990,1250
  rectangle net NetQ7_5: 765,677.61 990,850
  rectangle net NetQ10_5: 765,280 990,450
  rectangle net NetD1_1: 445,55.46 630,1595
  rectangle net NetF1_1: 110,935 400,1050
  rectangle net NetF2_2: 4160,655 4390,760
  rectangle net CHG/LOAD: 3890,460 4085,795
  rectangle net GND: 2465,335 2835,425
  rectangle net NetF1_1: 105,935 220,1245
  rectangle net NetF2_2: 4290,450 4390,750
  rectangle net GND: 3905,120 4065,300
  rectangle net GND: 65,1435 240,1590
  rectangle net NetQ1_5: 700,1480 990,1625
  text ".CopyrightYear" at 1228,53 h60
  text "TI" at 1504,53 h60
  text "©" at 1134,51 h105
  text ".Layer_Name" at 577,-858.49 h60
Bottom Layer:
  rectangle net NetD1_1: 425,200 650,1525
  rectangle net NetQ1_5: 700,1479.96 986.81,1625
  rectangle net NetQ4_5: 760,1082.61 990,1250
  rectangle net NetQ7_5: 765,677.61 990,850
  rectangle net NetQ10_5: 775,282.61 986.81,450
  rectangle net NetC1_1: 1150,285 1285,1595
  text "UL94V-0" at 3745,290 h60
  text "MADE IN U.S." at 3745,185 h60
  text ".Layer_Name" at 577,-858.49 h60

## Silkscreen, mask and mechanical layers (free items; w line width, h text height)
Top Overlay:
  lines w10: 1910,795 1910,1060 1950,1100 1950,1255 1970,1275 2560,1275 2620.09,1214.91 2620.09,905.09 2490,775 1930,775 1910,795
  text "Gauge Booster Pack" at 1335,1545 h90
  text "bq27421YZF" at 1930,1400 h90
  text "UNIT 1" at 1580,1385 h50
  text "Gauge" at 2230,1290 h40
  text "+" at 240,1160 h40
  text "-" at 4230,1160 h40
  text "Cell" at 295,1125 h40
  text "UNIT 2" at 1745,1125 h50
  text "Load/Chg" at 4145,1075 h40
  text "+" at 265,975 h40
  text "-" at 275,830 h40
  text "-" at 4185,825 h40
  text "TS" at 280,695 h40
  text "+" at 4190,685 h40
  text "+" at 4225,475 h40
  text "-" at 245,465 h40
  text ".Layer_Name" at 577,-858.49 h60
Bottom Overlay:
  rectangle: 2779,60 3079,160
  text ".PRJ_Number" at 3745,70 h60
  text ".PCB_Rev" at 2740,65 h60
  text "-" at 3144,59.5 h60
  text ".Layer_Name" at 577,-858.49 h60
Top Paste:
  text ".Layer_Name" at 577,-858.49 h60
Bottom Paste:
  text ".Layer_Name" at 577,-858.49 h60
Top Solder:
  text ".Layer_Name" at 577,-858.49 h60
  text ".Layer_Name" at 577,-858.49 h60
Bottom Solder:
  text ".Layer_Name" at 577,-858.49 h60
Drill Guide:
  text ".Layer_Name" at 577,-858.49 h60
M1 Board Outline:
  the board outline again, w10
  text ".Layer_Name" at 577,-858.49 h60
M2 Board Dimensions:
  rectangle: -0.5,-285.5 124.5,-160.5
  rectangle: 124.5,-410.5 499.5,-285.5
  lines w7: -0.5,-285.5 999.5,-285.5 ; 124.5,-410.5 124.5,-160.5 ; 249.5,-410.5 249.5,-160.5 ; 499.5,-410.5 499.5,-160.5 ; 749.5,-410.5 749.5,-160.5 ; -0.5,-410.5 999.5,-410.5 999.5,-160.5 -0.5,-160.5 -0.5,-410.5
  lines w10: -0.5,-475.5 -0.5,-455.5 ; 59.5,-485.5 -0.5,-465.5 ; 59.5,-445.5 -0.5,-465.5 ; 223.58,-465.5 -0.5,-465.5 ; 775.42,-465.5 999.5,-465.5 ; 939.5,-485.5 999.5,-465.5 ; 939.5,-445.5 999.5,-465.5 ; 999.5,-475.5 999.5,-455.5
  text "1000 (mil)" at 233.58,-501.49 h60
  text ".Layer_Name" at 577,-858.49 h60
M3 3D STEP Top:
  text ".Layer_Name" at 577,-858.49 h60
M4 3D STEP Bottom:
  text ".Layer_Name" at 577,-858.49 h60
M5 Assembly Top:
  lines w10: -292,-930.17 6308,-930.17 ; -292,-726.83 6310,-726.83 ; -292,-523.5 -292,-1133.5 3713,-1133.5 6310,-1133.5 6310,-523.5 -291.5,-523.5 -291.5,-1133.5 1284,-1133.5 ; 2173,-1133.5 2173,-523.5 ; 3440,-726.83 3440,-523.5 ; 4280,-726.83 4280,-523.5 ; 4902,-1140 4902,-937.17
  text "COMPONENTS MARKED 'DNP' SHOULD NOT BE POPULATED." at 1153.5,-318.5 h60
  text "ASSEMBLY VARIANT:" at 1153,-434 h60
  text ".VariantName" at 2189,-434 h60
  text "PCB VIEWED FROM TOP SIDE" at -228.5,-655.67 h60
  text "BOARD #:" at 2248,-655.67 h60
  text ".PRJ_Number" at 2793.5,-655.67 h60
  text "REV:" at 3638,-655.67 h60
  text ".PCB_Rev" at 3929.5,-655.67 h60
  text "SVN REV:" at 4476,-655.67 h60
  text ".VersionControl_RevNumber" at 4982,-655.67 h60
  text "IGNORE ->" at -228.5,-858.49 h60
  text "PLOT NAME =" at -228.5,-1064.34 h60
  text ".plot_File_Name" at 577,-1064.34 h60
  text "GENERATED    :" at 2250,-1064.34 h60
  text ".Print_Date" at 3119.5,-1064.34 h60
  text ".Print_Time" at 3848.5,-1064.34 h60
  text "TEXAS INSTRUMENTS" at 5113,-1064.34 h60
M6 Assembly Bottom:
  lines w10: -292.5,-727.33 6309.5,-727.33 ; -290.5,-930.67 6309.5,-930.67 ; 1115.5,-1140.5 1115.5,-937.67 ; 1737.5,-727.33 1737.5,-524 ; 2577.5,-727.33 2577.5,-524 ; 3844.5,-1134 3844.5,-524 ; 4733.5,-1134 6309,-1134 6309,-524 -292.5,-524 -292.5,-1134 2304.5,-1134 6309.5,-1134 6309.5,-524
  text "COMPONENTS MARKED 'DNP' SHOULD NOT BE POPULATED." at 6102,-318 h60
  text ".VariantName" at 5058,-434 h60
  text "ASSEMBLY VARIANT:" at 6097,-434 h60
  text ".VersionControl_RevNumber" at 1035.5,-656.17 h60
  text "SVN REV:" at 1541.5,-656.17 h60
  text ".PCB_Rev" at 2088,-656.17 h60
  text "REV:" at 2379.5,-656.17 h60
  text ".PRJ_Number" at 3224,-656.17 h60
  text "BOARD #:" at 3769.5,-656.17 h60
  text "PCB VIEWED FROM BOTTOM SIDE" at 6246,-656.17 h60
  text "IGNORE ->" at 2547.85,-858.49 h60
  text "TEXAS INSTRUMENTS" at 904.5,-1064.84 h60
  text ".Print_Time" at 2169,-1064.84 h60
  text ".Print_Date" at 2898,-1064.84 h60
  text "GENERATED    :" at 3767.5,-1064.84 h60
  text ".plot_File_Name" at 5440.5,-1064.84 h60
  text "PLOT NAME =" at 6246,-1064.84 h60
M9 Title Sheet:
  drawing of 57 lines, arcs and shapes, not listed
  text "1" at 739.84,8036.5 h70
  text "2" at 3235.5,8036.5 h70
  text "3" at 5724.84,8036.5 h70
  text "4" at 8231.51,8036.5 h70
  text "5" at 10730.5,8036.5 h70
  text "6" at 13235.5,8036.5 h70
  text "A" at -416.5,6893.5 h70
  text "A" at 14383.5,6893.5 h70
  text "B" at -416.5,4513.5 h70
  text "B" at 14383.5,4513.5 h70
  text "C" at -416.5,2138.5 h70
  text "C" at 14383.5,2138.5 h70
  text "PROJECT TITLE:" at 11343.5,277.5 h45
  text ".PRJ_Title" at 11393.5,144.17 h70
  text "DESIGNED FOR:" at 11343.5,-23.5 h45
  text ".PRJ_Customer" at 11393.5,-163.5 h70
  text "D" at -416.5,-231.5 h70
  text "D" at 14383.5,-231.5 h70
  text "FILE NAME:" at 11343.5,-323.5 h45
  text ".PCB_File_Name_No_Path" at 11393.5,-443.5 h70
  text "Texas Instruments (TI) and/or its licensors do not warrant the accuracy or completeness of this specification" at 6374,-605.34 h45
  text "ENGINEER:" at 11343.5,-613.5 h45
  text "LAYOUT BY:" at 12848.5,-613.5 h45
  text "or any information contained therein. TI and/or its licensors do not warrant that this design will meet" at 6329.01,-718 h45
  text ".PRJ_Engineer" at 11393.5,-768.49 h70
  text ".PCB_Layout" at 12899,-768.49 h70
  text "the specifications, will be suitable for your application or fit for any particular purpose, or will operate in" at 6329.01,-830.67 h45
  text ".Layer_Name" at 577,-858.49 h60
  text "ALTIUM DESIGNER VERSION:" at 12848.5,-923.5 h45
  text "an implementation. TI and/or its licensors do not warrant that the design is production worthy. You should" at 6329.01,-943.33 h45
  text "completely validate and test your design implementation to confirm the system functionality for your application." at 6374,-1056 h45
  text ".print_Scale" at 11393.5,-1056.83 h70
  text ".Application_BuildNumber" at 12899,-1056.83 h70
  text "1" at 739.84,-1263.5 h70
  text "2" at 3235.5,-1263.5 h70
  text "3" at 5724.84,-1263.5 h70
  text "4" at 8231.51,-1263.5 h70
  text "5" at 10730.5,-1263.5 h70
  text "6" at 13235.5,-1263.5 h70
M10 Fab Notes:
  drawing of 222 lines, arcs and shapes, not listed
  text "Layer Stack Up Detail for: PR2183E1_PCB.PcbDoc" at 11360,7666.77 h43
  text "Layer" at 11360,7608.35 h21
  text "Gerber" at 12357.17,7608.35 h21
  text "Copper" at 13078.24,7608.35 h21
  text "Dielectric" at 13833.59,7608.35 h21
  text "Name" at 11360,7566.35 h21
  text "Document" at 12357.17,7566.35 h21
  text "Thickness" at 13078.24,7566.35 h21
  text "Material" at 13833.59,7566.35 h21
  text "Top Solder Mask" at 11360,7505.78 h29
  text "(.GTS)" at 12357.17,7505.78 h29
  text "Solder Resist" at 13833.59,7505.78 h29
  text "Top Layer" at 11360,7419.84 h29
  text "(.GTL)" at 12357.17,7419.84 h29
  text "2.8mil" at 13078.24,7419.84 h29
  text "FR-4" at 13833.59,7376.88 h29
  text "MidLayer1" at 11360,7333.91 h29
  text "(.G1)" at 12357.17,7333.91 h29
  text "2.8mil" at 13078.24,7333.91 h29
  text "FR-4" at 13833.59,7290.94 h29
  text "MidLayer2" at 11360,7247.97 h29
  text "(.G2)" at 12357.17,7247.97 h29
  text "2.8mil" at 13078.24,7247.97 h29
  text "FR-4" at 13833.59,7205 h29
  text "Bottom Layer" at 11360,7162.03 h29
  text "(.GBL)" at 12357.17,7162.03 h29
  text "2.8mil" at 13078.24,7162.03 h29
  text "Bottom Solder Mask" at 11360,7076.09 h29
  text "(.GBS)" at 12357.17,7076.09 h29
  text "Solder Resist" at 13833.59,7076.09 h29
  text "DESIGN INFORMATION" at 12381.02,6810 h60
  text "(REFER ALSO ARRAY/PANEL PROFILING INFORMATION)" at 12019.46,6648.29 h60
  text "BOARD SIZE" at 11333.46,6644 h60
  text "1700MIL" at 11795.78,6516.18 h60
  text "X" at 12301.46,6516.18 h60
  text "4500MIL" at 12532.78,6516.18 h60
  text "Number of Layers :" at 11736.46,6319 h60
  text "4" at 12831.27,6309 h60
  text "MIN. TRACK WIDTH:" at 11736.46,6180 h60
  text "6" at 12832.7,6180 h60
  text "MIL" at 12987.46,6180 h60
  text "MIN. CLEARANCE:" at 11736.46,6048 h60
  text "5" at 12832.7,6048 h60
  text "MIL" at 12987.46,6048 h60
  text "MIN. VIA PAD SIZE:" at 11736.46,5916 h60
  text "18" at 12802.71,5916 h60
  text "MIL" at 12987.46,5916 h60
  text "0.05mm (2MIL)" at 12431.46,5774.29 h60
  text "MINIMUM ANNULAR RING" at 11407.23,5770 h60
  text "EXTERNAL" at 13139.46,5770 h60
  text "PER" at 11607.23,5652 h60
  text "IPC-D-275 CLASS 2 LEVEL C" at 11827.23,5652 h60
  text "MIL, HOLES" at 13315.46,5539.71 h60
  text "+/-" at 12923,5539 h60
  text "+/-" at 13777,5539 h60
  text "REGISTRATION TOLERANCES:" at 11407.23,5534 h60
  text "METAL" at 12607,5534 h60
  text "5" at 13183.2,5534 h60
  text "3" at 14016.2,5534 h60
  text "MIL" at 14132.46,5534 h60
  text "MATERIAL:" at 11332.46,5324.54 h60
  text "FR-4 High Tg" at 12318.9,5184.21 h60
  text "FR-408" at 11753.46,5175.64 h60
  text "X" at 12165.46,5175.64 h60
  text "OTHER" at 13241.46,5175.64 h60
  text "62 MIL (1.6mm) +/-10%" at 12073.56,5012.92 h60
  text "THICKNESS:" at 11407.23,5008.64 h60
  text "X" at 11945.4,5008.64 h60
  text "OTHER" at 13358.46,5008.64 h60
  text "TOLERANCE:" at 11407.23,4850.64 h60
  text "X" at 12246.53,4850.64 h60
  text "ANSI IPC-6012 TYPE 3 CLASS 2" at 12433.48,4850.64 h60
  text "OTHER +/-" at 12433.46,4694.64 h60
  text "BOW & TWIST:" at 11407.23,4537.64 h60
  text "X" at 12246.53,4537.64 h60
  text "ANSI IPC-6012 TYPE 3 CLASS 2" at 12433.48,4537.64 h60
  text "OTHER +/-" at 12433.46,4379.13 h60
  text "COPPER THICKNESS (FINISHED):" at 11332.46,4243.64 h60
  text "1.4MIL (1oz)" at 12212.46,4090.92 h60
  text "2MIL (1.4oz)" at 12979.46,4090.92 h60
  text "2.8MIL (2oz)" at 13706.46,4090.92 h60
  text "X" at 13585,4090 h60
  text "OUTER:" at 11689.46,4086.64 h60
  text "1.4MIL (1oz)" at 12212.46,3933.92 h60
  text "2.8MIL (2oz)" at 12979.46,3933.92 h60
  text "N/A" at 13706,3934.29 h60
  text "INNER SIGNAL:" at 11400.38,3929.64 h60
  text "X" at 12850,3925 h60
  text "DRILLING:" at 11332.46,3790.64 h60
  text "REFERENCE:" at 11407.23,3673.64 h60
  text "X" at 12055.46,3673.64 h60
  text "AS SHOWN" at 12242.46,3673.64 h60
  text "X" at 12956.46,3673.64 h60
  text "NC_DRILL FILES" at 13093.46,3673.64 h60
  text "PTH MIN COPPER THICKNESS:" at 11407.23,3515.64 h60
  text "X" at 12757.46,3515.64 h60
  text "1MIL" at 12894.46,3515.64 h60
  text "OTHER" at 13391.46,3515.64 h60
  text "BOARD FINISH:" at 11332.46,3356.64 h60
  text "SILKSCREEN:" at 11487.68,3238.64 h60
  text "X" at 12436.46,3238.64 h60
  text "TOP" at 12562.46,3238.64 h60
  text "X" at 12946.46,3238.64 h60
  text "BOTTOM" at 13073.46,3238.64 h60
  text "SILKSCREEN COLOR:" at 11487.68,3071.64 h60
  text "X" at 12435.42,3071.64 h60
  text "WHITE" at 12562.46,3071.64 h60
  text "OTHER" at 13073.46,3071.64 h60
  text "SOLDER RESIST COLOR:" at 11487.68,2901.64 h60
  text "GREEN" at 12182.46,2742.44 h60
  text "BLUE" at 12773.46,2742.44 h60
  text "OTHER" at 13311.46,2742.44 h60
  text "RED" at 13653.46,2742.44 h60
  text "X" at 13160,2740 h60
  text "IMMERSION GOLD (ENIG)" at 12393.46,2553.92 h60
  text "ENEPIG" at 13731,2550.64 h60
  text "SURFACE FINISH:" at 11332.46,2549.64 h60
  text "X" at 12206.51,2549.64 h60
  text "IMM. TIN/SILVER OR EQUIV" at 11662,2392.64 h60
  text "OTHER" at 13093.46,2392.64 h60
  text "ARRAY/PANEL:" at 11332.46,2213.64 h60
  text "CUT AND TRIM PER MECH LAYER 1" at 12393.46,2209.35 h60
  text "N.C. ROUTE" at 12393.46,2057.64 h60
  text "X" at 13072.46,2057.64 h60
  text "V. SCORE" at 13259.46,2057.64 h60
  text "CERTIFICATION:" at 11332.46,1920.64 h60
  text "MATERIALS AND WORKMANSHIP FOR ALL PCBS" at 12057.46,1920.64 h60
  text "TO MEET OR EXCEED THE REQUIREMENTS OF:" at 12057.46,1822.64 h60
  text "X" at 11683.96,1686.13 h60
  text "ANSI IPC-A-600F CLASS ->" at 11822.96,1686.13 h60
  text "X" at 13462.02,1686.13 h60
  text "2" at 13580.96,1686.14 h60
  text "1" at 13265.96,1684.64 h60
  text "3" at 13934.96,1684.64 h60
  text "X" at 11686.02,1526.64 h60
  text "UL 94V-0" at 11822.96,1526.64 h60
  text "X" at 12498.02,1526.64 h60
  text "RoHS" at 12634.96,1526.64 h60
  text "OTHER" at 13279.36,1526.64 h60
  text "PER ORDER" at 13676.42,1526.64 h60
  text "ADDITIONAL REQUIREMENTS:" at 11332.46,1385.64 h60
  text "MICROSECTION:" at 11407.23,1270.64 h60
  text "YES" at 12312.96,1270.64 h60
  text "REQUIRED" at 13174.46,1114.49 h60
  text "BARE BOARD ELEC. TEST:" at 11407.23,1111.64 h60
  text "NONE" at 12712.96,1111.64 h60
  text "X" at 13047.46,1111.64 h60
  text "PER ORDER" at 13766.46,1111.64 h60
  text "MANUFACTURER'S UL:" at 11407.23,954.64 h60
  text "RAIL" at 12572.96,950.35 h60
  text "METAL" at 13064.77,950.35 h60
  text "X" at 13440,950 h60
  text "SILK" at 13576.46,950.35 h60
  text ".Layer_Name" at 577,-858.49 h60
M11 Gerber Information:
  lines w10: -292,-930.17 6308,-930.17 ; -292,-726.83 6310,-726.83 ; -292,-523.5 -292,-1133.5 3713,-1133.5 6310,-1133.5 6310,-523.5 -291.5,-523.5 -291.5,-1133.5 1284,-1133.5 ; 2173,-1133.5 2173,-523.5 ; 3440,-726.83 3440,-523.5 ; 4280,-726.83 4280,-523.5 ; 4902,-1140 4902,-937.17
  text "ALL ARTWORK VIEWED FROM TOP SIDE" at -228.5,-655.67 h60
  text "BOARD #:" at 2248,-655.67 h60
  text ".PRJ_Number" at 2793.5,-655.67 h60
  text "REV:" at 3638,-655.67 h60
  text ".PCB_Rev" at 3929.5,-655.67 h60
  text "SVN REV:" at 4476,-655.67 h60
  text ".VersionControl_RevNumber" at 4982,-655.67 h60
  text "LAYER NAME =" at -228.5,-858.49 h60
  text "PLOT NAME =" at -228.5,-1064.34 h60
  text ".plot_File_Name" at 577,-1064.34 h60
  text "GENERATED    :" at 2250,-1064.34 h60
  text ".Print_Date" at 3119.5,-1064.34 h60
  text ".Print_Time" at 3848.5,-1064.34 h60
  text "TEXAS INSTRUMENTS" at 5113,-1064.34 h60
M12 Stackup:
  text "The Stackup Legend below this is static." at 11605.5,7874.5 h60
  text "If you change the stackup, update the Legend." at 11615.5,7784.5 h60
  text ".Layer_Name" at 577,-858.49 h60
M13 Component Bodies Top:
  text ".Layer_Name" at 577,-858.49 h60
M14 Component Bodies Bottom:
  text ".Layer_Name" at 577,-858.49 h60
M15 Courtyards Top:
  text ".Layer_Name" at 577,-858.49 h60
M16 Courtyards Bottom:
  text ".Layer_Name" at 577,-858.49 h60
Drill Drawing:
  circle w1: c5167.72,1906.72 r24.89
  lines w1: 5142.83,1135.24 5142.83,1147.68 5155.27,1160.12 5142.83,1172.57 5142.83,1185.01 5155.27,1185.01 5167.72,1172.57 5180.16,1185.01 5192.6,1185.01 5192.6,1172.57 5180.16,1160.12 5192.6,1147.68 5192.6,1135.24 5180.16,1135.24 5167.72,1147.68 5155.27,1135.24 5142.83,1135.24 ; 5142.83,1297 5155.27,1297 5155.27,1284.56 5180.16,1284.56 5180.16,1297 5192.6,1297 5192.6,1321.89 5180.16,1321.89 5180.16,1334.33 5155.27,1334.33 5155.27,1321.89 5142.83,1321.89 5142.83,1297 ; 5142.83,1433.88 5167.72,1446.32 5192.6,1433.88 5180.16,1458.76 5192.6,1483.65 5167.72,1471.21 5142.83,1483.65 5155.27,1458.76 5142.83,1433.88 ; 5142.83,1595.64 5155.27,1595.64 5167.72,1583.2 5180.16,1595.64 5192.6,1595.64 5180.16,1608.08 5192.6,1620.53 5180.16,1620.53 5167.72,1632.97 5155.27,1620.53 5142.83,1620.53 5155.27,1608.08 5142.83,1595.64 ; 5142.83,1782.29 5192.6,1782.29 5167.72,1732.52 5142.83,1782.29 ; 5142.83,2031.16 5192.6,2031.16 5192.6,2080.93 5142.83,2080.93 5142.83,2031.16
  lines w12: 5075,1090.44 7193.02,1090.44 ; 5075,2135.68 7193.02,2135.68 ; 5445.36,941.12 5445.36,2285 ; 5802.36,941.12 5802.36,2285 ; 6463.93,941.12 6463.93,2285 ; 6748.07,941.12 6748.07,2285 ; 5075,941.12 7193.02,941.12 7193.02,2285 5075,2285 5075,941.12
  text "Symbol" at 5164.59,2180.48 h72
  text "Quantity" at 5490.16,2180.48 h72
  text "Finished Hole Size" at 5847.16,2180.48 h72
  text "Plated" at 6508.72,2180.48 h72
  text "Hole Type" at 6792.86,2180.48 h72
  text "16" at 5490.16,2031.16 h60
  text "8.00mil (0.203mm)" at 5847.16,2031.16 h60
  text "PTH" at 6508.72,2031.16 h60
  text "Round" at 6792.86,2031.16 h60
  text "75" at 5490.16,1881.84 h60
  text "12.00mil (0.305mm)" at 5847.16,1881.84 h60
  text "PTH" at 6508.72,1881.84 h60
  text "Round" at 6792.86,1881.84 h60
  text "5" at 5490.16,1732.52 h60
  text "26.00mil (0.660mm)" at 5847.16,1732.52 h60
  text "PTH" at 6508.72,1732.52 h60
  text "Round" at 6792.86,1732.52 h60
  text "23" at 5490.16,1583.2 h60
  text "40.00mil (1.016mm)" at 5847.16,1583.2 h60
  text "PTH" at 6508.72,1583.2 h60
  text "Round" at 6792.86,1583.2 h60
  text "20" at 5490.16,1433.88 h60
  text "45.28mil (1.150mm)" at 5847.16,1433.88 h60
  text "PTH" at 6508.72,1433.88 h60
  text "Round" at 6792.86,1433.88 h60
  text "3" at 5490.16,1284.56 h60
  text "50.00mil (1.270mm)" at 5847.16,1284.56 h60
  text "PTH" at 6508.72,1284.56 h60
  text "Round" at 6792.86,1284.56 h60
  text "3" at 5490.16,1135.24 h60
  text "55.12mil (1.400mm)" at 5847.16,1135.24 h60
  text "PTH" at 6508.72,1135.24 h60
  text "Round" at 6792.86,1135.24 h60
  text "145 Total" at 5490.16,985.92 h60
  text ".legend" at 5122.5,725.5 h60
  text "Drill Table" at 5147.5,540.5 h60
  text ".Layer_Name" at 577,-858.49 h60

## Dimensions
0,-17.36 to 1350,390 on M2 Board Dimensions
0,0 to 0,1700 on M2 Board Dimensions
4500,0 to 0,0 on M2 Board Dimensions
